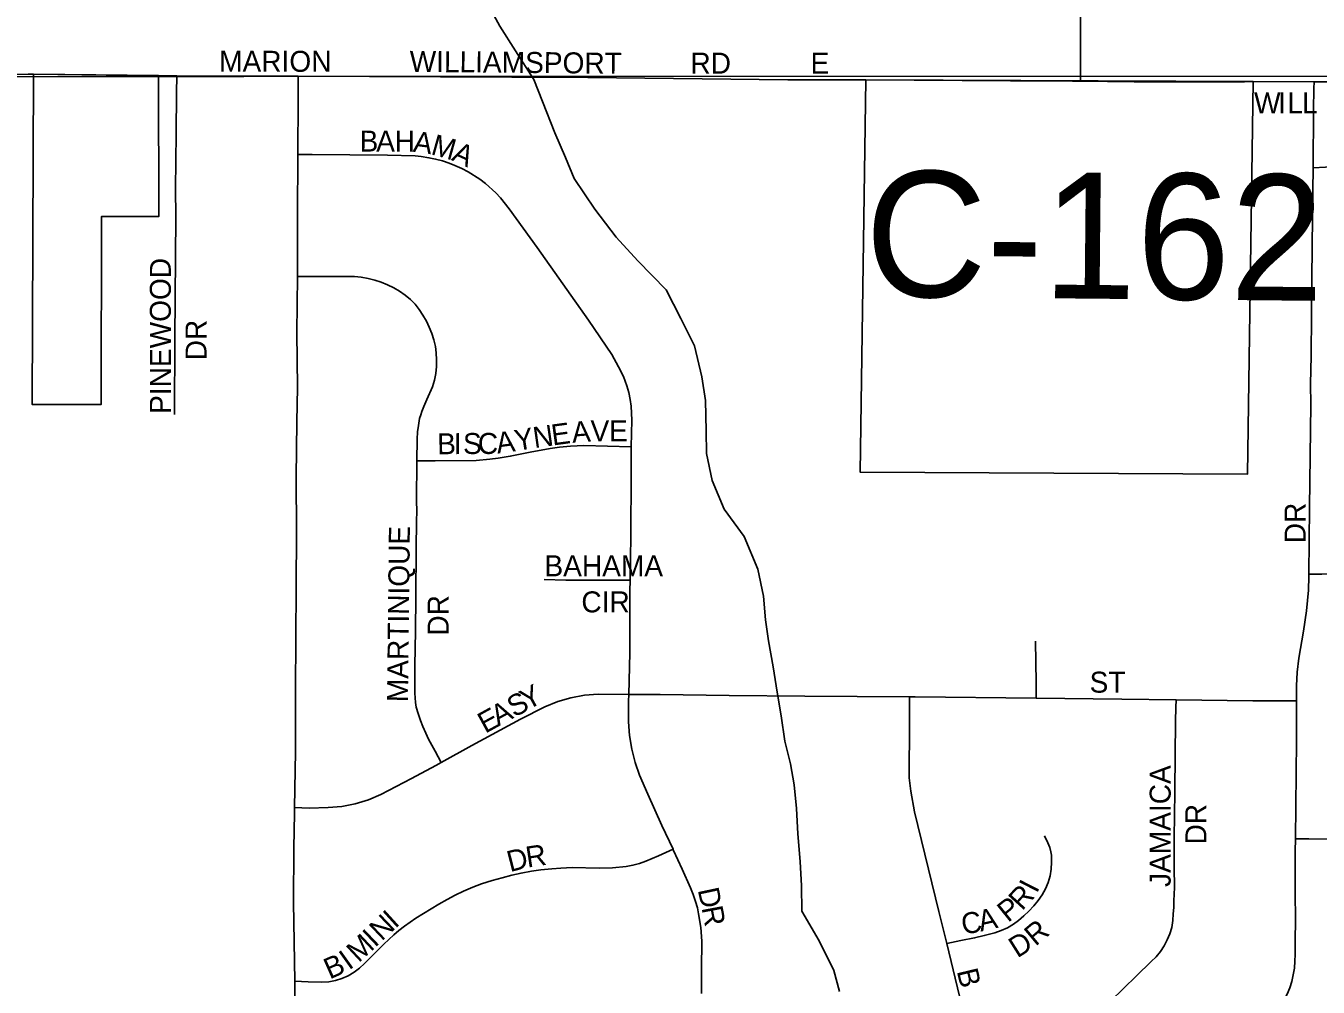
# Model space of a CAD drawing. Extents: x 1584893 to 1934202, y 663575 to 1091909.
# Drawn here: x 1795360 to 1798437, y 950884 to 953173 of the extents above; entities that cross this region are included whole.
import ezdxf

# ---------------------------------------------------------------- set-up
doc = ezdxf.new("R2010")
doc.units = 0
for name, color, linetype in [('GM_X_City_Street', 7, 'Continuous'), ('GM_X_City_Street_Text', 7, 'Continuous'), ('GM_X_Corporation', 7, 'Continuous'), ('GM_X_County_Road', 7, 'Continuous'), ('GM_X_County_Road_Text', 7, 'Continuous'), ('GM_X_Minor_River', 7, 'Continuous'), ('GM_X_Section', 7, 'Continuous')]:
    doc.layers.add(name, color=color, linetype=linetype)

msp = doc.modelspace()

# ---------------------------------------------------------------- linework, layer by layer
at = {"layer": 'GM_X_City_Street'}
for points in [[(1797871.2, 953041.3), (1797871.2, 953075), (1797871, 953302.5), (1797871.5, 953335.1), (1797871, 953350.7), (1797869.6, 953357.4), (1797866.8, 953363.6), (1797862.4, 953367.9), (1797856.6, 953371.3), (1797841.8, 953374.1), (1797809.5, 953374.9), (1797793.1, 953375.3), (1797783.4, 953376.7), (1797777.9, 953378.6), (1797773.6, 953381.6), (1797769, 953386.4), (1797765.5, 953391.4), (1797762.2, 953399.2), (1797760.9, 953408.7), (1797761.5, 953456.3)], [(1798426.8, 953039.9), (1798490, 953039.7), (1798605.6, 953042.3), (1799002.1, 953059.6), (1799032.2, 953060.8)], [(1795208.1, 953057.7), (1795225.2, 953057.7), (1795365.1, 953057.8), (1795378.3, 953058)], [(1795714, 952248.1), (1795714.7, 952428.8), (1795716.6, 952718.2), (1795715.8, 952785.6), (1795717.9, 952916), (1795718.9, 953014), (1795719.4, 953054.5)], [(1795719.4, 953054.5), (1795893.2, 953053.7), (1796008.1, 953053.1)], [(1796007.3, 952867.1), (1796008, 952998.2), (1796008, 953014.5), (1796008.1, 953053.1)], [(1796008.1, 953053.1), (1796517.3, 953050.8), (1796698.1, 953049.9), (1797174.4, 953045), (1797349.7, 953044.6), (1797359.7, 953044.6)], [(1798281.9, 953040.4), (1798426.8, 953039.9)], [(1798424.5, 952834.9), (1798425.9, 952973), (1798426.6, 953023.8), (1798426.8, 953039.9)], [(1796006.3, 952576.7), (1796006.5, 952606.3), (1796006.6, 952720.8), (1796007.3, 952867.1)], [(1796801.1, 952171.1), (1796803, 952234.4), (1796800.7, 952267.3), (1796798.9, 952283.1), (1796795.3, 952300), (1796791, 952316.1), (1796782.8, 952337.9), (1796771, 952361.4), (1796754.7, 952390.4), (1796699.8, 952472), (1796577.3, 952645), (1796510.6, 952737.7), (1796490.3, 952763.9), (1796478.8, 952775.9), (1796454.2, 952798.1), (1796441, 952808.1), (1796412.7, 952825.8), (1796397.9, 952833.3), (1796381.6, 952840.5), (1796367.4, 952846.2), (1796351.7, 952851.4), (1796335.3, 952855.9), (1796319.4, 952859.1), (1796301, 952862.2), (1796286.6, 952863.5), (1796221, 952865.1), (1796041.4, 952866.8), (1796007.3, 952867.1)], [(1798744.4, 952849.8), (1798683.1, 952847.4), (1798454.3, 952836.3), (1798424.5, 952834.9)], [(1798414.3, 951867.8), (1798416.3, 952025.9), (1798419, 952271.9), (1798418.4, 952321.1), (1798419.8, 952386.7), (1798421.1, 952485.1), (1798422.5, 952649.1), (1798423.9, 952780.4), (1798424.5, 952834.9)], [(1795999.7, 951311.6), (1796001.9, 951444.6), (1796002.1, 951591.7), (1796003.4, 951836.9), (1796004.4, 951967.8), (1796003.6, 952098.7), (1796005.1, 952229.9), (1796006.8, 952311.7), (1796005.2, 952442.6), (1796006.3, 952576.7)], [(1796291.1, 952137.5), (1796291.5, 952189.1), (1796292.4, 952206.1), (1796294.5, 952221.7), (1796297.4, 952237.8), (1796300, 952246.9), (1796302.6, 952255.2), (1796307.3, 952267.1), (1796314.9, 952283.7), (1796328, 952313.8), (1796332.6, 952329.5), (1796335.6, 952345.5), (1796337.4, 952361.8), (1796337.8, 952378), (1796337.1, 952394.3), (1796335.2, 952409.6), (1796331.3, 952425.3), (1796326.3, 952440.6), (1796320.4, 952455.6), (1796313.4, 952470.2), (1796305.3, 952484.3), (1796296.3, 952497.7), (1796286.5, 952510.3), (1796275.6, 952521.7), (1796263, 952532.2), (1796249.7, 952541.3), (1796235.9, 952549.5), (1796221.2, 952556.8), (1796206, 952562.6), (1796190.4, 952567.6), (1796174.6, 952571.7), (1796158.6, 952574.7), (1796142.4, 952576), (1796043.9, 952576.5), (1796006.3, 952576.7)], [(1796291.1, 952137.5), (1796318.5, 952137.5), (1796334.6, 952137.6), (1796432.2, 952138.5), (1796464.7, 952141.1), (1796484.4, 952143.6), (1796513, 952148.3), (1796560.8, 952158.1), (1796608.4, 952166.5), (1796630.1, 952169.8), (1796656.3, 952172.4), (1796688.3, 952173.9), (1796801.1, 952171.1)], [(1796798.4, 951853.2), (1796799.9, 951958.2), (1796801.2, 952105.5), (1796801.1, 952171.1)], [(1796348.8, 951419.4), (1796334.1, 951446.2), (1796318.3, 951474.8), (1796311.9, 951489), (1796304.9, 951504.8), (1796299.2, 951519), (1796293.7, 951535.7), (1796289.4, 951551.2), (1796287.7, 951561.8), (1796286.5, 951572.8), (1796285.9, 951584.1), (1796286.3, 951649.7), (1796287.9, 951731.6), (1796288.5, 951813.5), (1796289.3, 951928.2), (1796289.6, 951993.9), (1796290.6, 952017.9), (1796290.3, 952041.9), (1796291.1, 952137.5)], [(1798385.2, 951565.6), (1798385.3, 951601.8), (1798387, 951634.5), (1798390.6, 951667.1), (1798401.8, 951731.7), (1798408.9, 951780.3), (1798413.4, 951829.2), (1798414.3, 951861.9), (1798414.3, 951867.8)], [(1798414.3, 951867.8), (1798445.7, 951867.9), (1798734.5, 951868.8)], [(1796593.9, 951854.5), (1796645.5, 951853.1), (1796765.9, 951853.3), (1796798.4, 951853.2)], [(1796795.1, 951581.2), (1796797.8, 951679.8), (1796798, 951827.2), (1796798.4, 951853.2)], [(1797765.3, 951571.9), (1797764.9, 951608.7), (1797763.9, 951708.1)], [(1796348.8, 951419.4), (1796422, 951459.5), (1796537.3, 951522.3), (1796595.8, 951552), (1796626.1, 951564.4), (1796657.7, 951573.4), (1796690, 951579.1), (1796722.7, 951581.6), (1796795.1, 951581.2)], [(1796900.8, 951212.5), (1796874.3, 951269.1), (1796840.7, 951343.7), (1796821.2, 951388.5), (1796810.4, 951419.3), (1796802.4, 951451), (1796797.3, 951483.3), (1796794.9, 951516), (1796794.6, 951565.2), (1796795.1, 951581.2)], [(1796795.1, 951581.2), (1796870.3, 951580.8), (1797034.4, 951578.4), (1797214.8, 951577), (1797464, 951575.2)], [(1797552.2, 950988.2), (1797533.7, 951064.3), (1797475.9, 951301.9), (1797466.5, 951350.8), (1797462.6, 951382.4), (1797462.9, 951415.3), (1797463.6, 951480.9), (1797463.9, 951546.7), (1797464, 951575.2)], [(1797464, 951575.2), (1797477.3, 951575.1), (1797765.3, 951571.9)], [(1797765.3, 951571.9), (1797969.5, 951569.6), (1798098.2, 951568.2)], [(1797911.2, 950820.2), (1798004.5, 950910.9), (1798039.4, 950945), (1798050.6, 950956.7), (1798060.9, 950969.2), (1798069.9, 950982.7), (1798077.4, 950996.8), (1798083.6, 951011.3), (1798088.1, 951026.5), (1798090.7, 951042.5), (1798091.8, 951058.5), (1798092.7, 951073.7), (1798093.4, 951089.3), (1798094.4, 951121.2), (1798093.9, 951169.9), (1798094.1, 951243.9), (1798094.9, 951289.9), (1798095.6, 951353.2), (1798096.9, 951517.6), (1798097.7, 951550.2), (1798098.2, 951568.2)], [(1798098.2, 951568.2), (1798281.2, 951566.2), (1798346.9, 951565.8), (1798385.2, 951565.6)], [(1798382.6, 951237.1), (1798385, 951470.6), (1798385.2, 951565.6)], [(1795999.7, 951311.6), (1796034.1, 951310.6), (1796079.3, 951311.6), (1796111.9, 951314.6), (1796144.1, 951320.7), (1796175.3, 951330.3), (1796205.4, 951343.2), (1796278.2, 951380.8), (1796335.7, 951412.2), (1796348.8, 951419.4)], [(1796000, 950898.1), (1795997.4, 951085.7), (1795998, 951215.7), (1795999.4, 951297.4), (1795999.7, 951311.6)], [(1797552.2, 950988.2), (1797586.3, 950995), (1797618.6, 951001.4), (1797641.5, 951006.9), (1797666.6, 951013.8), (1797682.2, 951019), (1797697.2, 951025.6), (1797711.1, 951033.8), (1797723.6, 951042.8), (1797736.2, 951053.9), (1797747.7, 951064.7), (1797759.7, 951077.9), (1797770.2, 951090.5), (1797779.4, 951104), (1797787.4, 951118.1), (1797794.1, 951133), (1797798.3, 951148.8), (1797800.8, 951165.2), (1797801.9, 951181.6), (1797801.4, 951198.1), (1797800.4, 951206.4), (1797797.5, 951216.8), (1797793.2, 951227.6), (1797785.2, 951244.5)], [(1798226.8, 950725.7), (1798285.3, 950783.4), (1798321.1, 950817.2), (1798344.7, 950839.9), (1798354.6, 950852.9), (1798362.6, 950867.2), (1798368.9, 950882.4), (1798373.6, 950897.9), (1798377.2, 950913.6), (1798380, 950929.7), (1798381.3, 950946.1), (1798382.2, 950961.6), (1798381.6, 950994.4), (1798382.4, 951044.2), (1798381.6, 951109.8), (1798382.3, 951208.2), (1798382.6, 951237.1)], [(1798382.6, 951237.1), (1798414.5, 951236.9), (1798508.1, 951236.1)], [(1796000, 950898.1), (1796032.1, 950896.9), (1796064.7, 950895.6), (1796080.9, 950897), (1796096.8, 950900.3), (1796112.5, 950904.9), (1796127.5, 950911.4), (1796141.5, 950919.7), (1796154.4, 950929.5), (1796166.5, 950940.6), (1796212.3, 950986.7), (1796236, 951008.8), (1796248.1, 951019), (1796261.6, 951029.2), (1796288.1, 951048.2), (1796343.2, 951081.5), (1796363.1, 951093.1), (1796382.3, 951103.4), (1796401.9, 951112.5), (1796424.2, 951122.1), (1796444.5, 951130.2), (1796470.1, 951138.3), (1796493.6, 951144.8), (1796517, 951150.9), (1796538.8, 951155.6), (1796564.1, 951160.1), (1796586.2, 951163.3), (1796612.1, 951166.1), (1796633.5, 951167.2), (1796660.5, 951168.7), (1796724.8, 951167.7), (1796756.9, 951168), (1796789, 951171.2), (1796805.1, 951174.3), (1796820.9, 951178.4), (1796836.3, 951183.8), (1796866.2, 951197.1), (1796900.8, 951212.5)], [(1796968.2, 950869.2), (1796968.5, 950911.7), (1796968.7, 950944.5), (1796969.6, 950977.1), (1796969.5, 950993.5), (1796966.9, 951026.1), (1796961.4, 951058.4), (1796959, 951073.2), (1796954.5, 951088), (1796948.7, 951104.8), (1796942.6, 951120.9), (1796922.2, 951165), (1796902.2, 951209.8), (1796900.8, 951212.5)], [(1797582.6, 950863), (1797552.2, 950988.2)], [(1795995.8, 950170.8), (1795996.4, 950329.4), (1795997.6, 950410.2), (1795998.2, 950458.3), (1795998.2, 950571.1), (1795997.9, 950648.1), (1795999, 950728.5), (1796000, 950891.3), (1796000, 950898.1)]]:
    msp.add_lwpolyline(points, dxfattribs=at)
at = {"layer": 'GM_X_Corporation'}
for points in [[(1795378.3, 953058), (1795375, 952271.5), (1795539, 952271.5), (1795539.9, 952718.9), (1795676.3, 952718.9), (1795676, 953054.6)], [(1797359.7, 953044.6), (1797346.2, 952110.4), (1798268.3, 952105.6), (1798281.9, 953040.4)]]:
    msp.add_lwpolyline(points, close=True, dxfattribs=at)
at = {"layer": 'GM_X_County_Road'}
for points in [[(1795378.3, 953058), (1795608.3, 953054.7), (1795719.4, 953054.5)], [(1797359.7, 953044.6), (1797704.1, 953042.1), (1797851.6, 953041.5), (1797871.2, 953041.3)], [(1797871.2, 953041.3), (1797998.9, 953040), (1798261.1, 953040.2), (1798281.9, 953040.4)]]:
    msp.add_lwpolyline(points, dxfattribs=at)
at = {"layer": 'GM_X_Minor_River'}
msp.add_lwpolyline([(1796459.5, 953224.7), (1796488.7, 953172.3), (1796525.9, 953113.7), (1796569, 953045.1), (1796590.2, 952992.8), (1796619.2, 952918.3), (1796644.4, 952860), (1796665.7, 952809.6), (1796714.7, 952736.9), (1796765.7, 952670.2), (1796816.9, 952613.4), (1796884, 952544.5), (1796919, 952476), (1796952.1, 952411.5), (1796969.1, 952337.2), (1796978.3, 952281), (1796979.3, 952209), (1796980.5, 952154.9), (1796993.6, 952090.7), (1797022.7, 952022.3), (1797069.8, 951957.6), (1797102.7, 951879.1), (1797115.8, 951814.9), (1797121, 951758.8), (1797128.3, 951708.7), (1797139.4, 951646.5), (1797148.6, 951586.3), (1797157.8, 951530.2), (1797167, 951470), (1797180.2, 951415.8), (1797189.5, 951365.6), (1797194.8, 951309.5), (1797197.9, 951249.4), (1797203, 951183.3), (1797206.2, 951125.3), (1797207.3, 951065.2), (1797248.3, 950994.6), (1797283.4, 950924.1), (1797296.7, 950873.9)], dxfattribs=at)
at = {"layer": 'GM_X_Section'}
for points in [[(1793301.5, 958369.9), (1798586, 958327.6), (1798546, 953053.1), (1793211.7, 953051.5)], [(1793211.7, 953051.5), (1798546, 953053.1), (1798501.2, 947724.3), (1793155.7, 947768.8)]]:
    msp.add_lwpolyline(points, close=True, dxfattribs=at)

# ---------------------------------------------------------------- texts
at = {"layer": 'GM_X_City_Street_Text'}
for s, rotation, p in [('MARION', 0, (1795820.1, 953063.7)), ('WILLIAMSPORT', 359.4544, (1796273.4, 953063.7)), ('RD', 0, (1796942.1, 953059.3)), ('E', 0, (1797228.1, 953059.3)), ('W', 0, (1798284.1, 952964.5)), ('I', 0, (1798341.3, 952964.5)), ('L', 0, (1798363.3, 952964.5)), ('L', 0, (1798398.5, 952964.5)), ('B', 359.83, (1796154.4, 952873.9)), ('A', 359.8033, (1796194, 952873.8)), ('H', 359.8237, (1796238, 952873.6)), ('A', 351.9533, (1796280.2, 952873.6)), ('M', 344.2273, (1796322, 952867.8)), ('A', 335.6248, (1796371, 952854.1)), ('PINEWOOD', 90, (1795705.1, 952249.1)), ('DR', 90, (1795790.1, 952376.7)), ('A', 4.4859, (1796661.5, 952180.1)), ('V', 0.1967, (1796704.4, 952183.5)), ('E', 0, (1796748.4, 952183.7)), ('B', 0.4372, (1796339.4, 952152.9)), ('I', 0.4255, (1796378.9, 952153.2)), ('S', 0.4372, (1796400.9, 952153.4)), ('C', 0.4214, (1796436.1, 952153.6)), ('A', 7.7599, (1796482.7, 952154.4)), ('Y', 9.2352, (1796527.7, 952160.6)), ('N', 8.025, (1796570.8, 952167.6)), ('E', 7.7012, (1796614.3, 952173.7)), ('DR', 90, (1798406.7, 951941.1)), ('MARTINIQUE', 89.3557, (1796269.6, 951562.5)), ('BAHAMA', 0, (1796594.5, 951862.5)), ('DR', 90, (1796366.5, 951721.1)), ('CIR', 0, (1796682.5, 951776.5)), ('ST', 0, (1797892.5, 951585.3)), ('S', 28.7314, (1796523, 951525.4)), ('Y', 28.4814, (1796553.8, 951542.3)), ('A', 28.7256, (1796484.4, 951504.3)), ('E', 28.7282, (1796453.5, 951487.3)), ('JAMAICA', 90, (1798085.5, 951122.7)), ('DR', 90, (1798170.5, 951223.9)), ('D', 14.3543, (1796512.6, 951157.9)), ('R', 8.6797, (1796554, 951168.6)), ('R', 47.7083, (1797731.8, 951064.4)), ('I', 62.889, (1797766.7, 951105.6)), ('D', 282.0429, (1796959.4, 951115.9)), ('P', 38.7568, (1797698.2, 951036.6)), ('I', 42.2472, (1796239, 951022.3)), ('R', 280.6764, (1796968.5, 951073.2)), ('C', 10.105, (1797591.7, 951008.8)), ('A', 12.6634, (1797633, 951016.2)), ('N', 43.4866, (1796207.2, 950992.2)), ('R', 39.9861, (1797763.6, 950980.1)), ('M', 43.054, (1796152.4, 950940.7)), ('I', 43.4673, (1796191.2, 950977)), ('D', 32.1745, (1797720.4, 950952.3)), ('I', 35.5364, (1796129, 950923.5)), ('B', 23.7948, (1796083.3, 950902.1)), ('B', 283.5827, (1797576, 950922.5))]:
    msp.add_text(s, height=50, rotation=rotation, dxfattribs=at).set_placement(p)
at = {"layer": 'GM_X_County_Road_Text'}
msp.add_text('C-162', height=300, rotation=359.4443, dxfattribs=at).set_placement((1797356.5, 952528.8))

doc.saveas('drawing.dxf')
